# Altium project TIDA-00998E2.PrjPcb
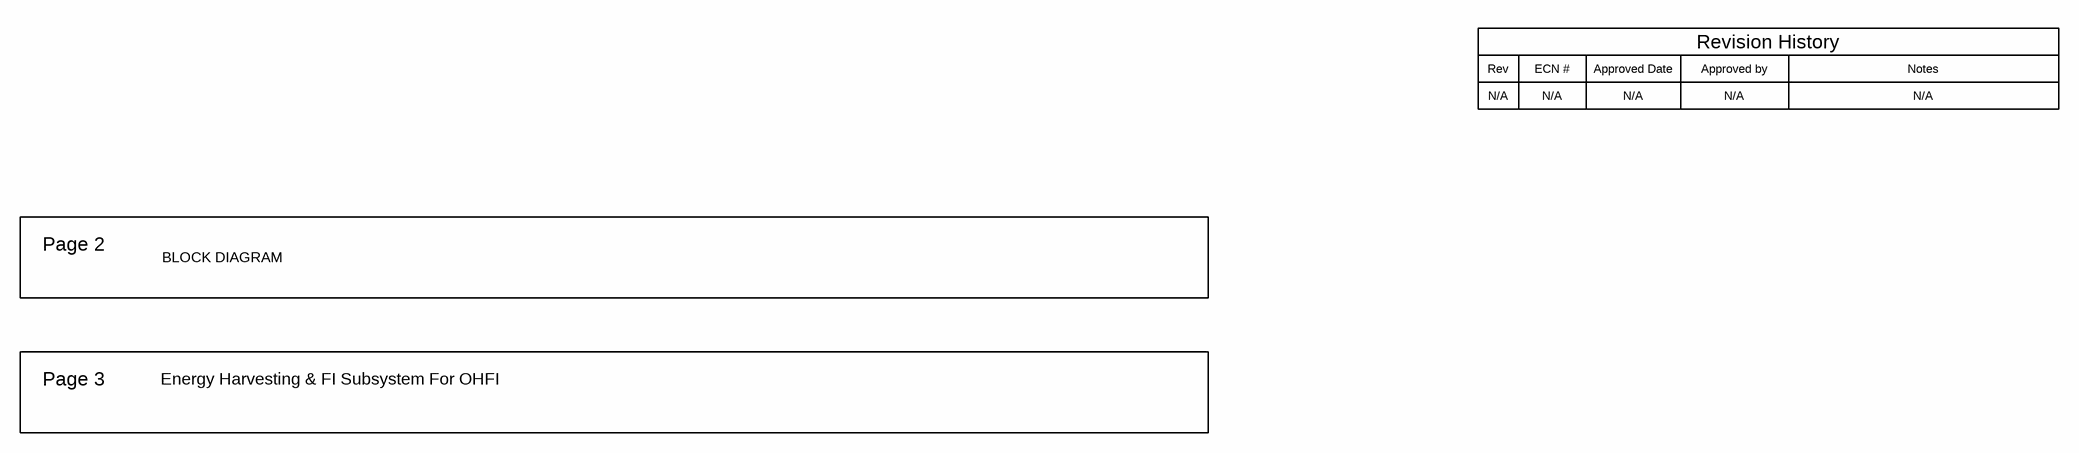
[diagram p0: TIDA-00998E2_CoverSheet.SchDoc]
CopyrightYear: 2016; EVM_Orderable: N/A; PCB_Layout: Manjunath M; PCB_Rev: E2; PRJ_Customer: Public Release; PRJ_Engineer: Murali; PRJ_Number: TIDA-00998; PRJ_Title: Energy Harvesting & FI Subsystem For OHFI; SCH_Rev: E2; TechSupport: http://www.ti.com/support; TID: TIDA-00998
4 sheets, 111 parts. Net scope: global (net labels, ports and power ports of the same name join across sheets).
Board file: TIDA-00998E2.PcbDoc
Sheets:
  TIDA-00998E2_CoverSheet.SchDoc
  TIDA-00998E2_Block Diagram.SchDoc
  TIDA-00998E2_BlankSheet.SchDoc
  TIDA-00998E2_EVM_Hardware.SchDoc

## Sheet TIDA-00998E2_CoverSheet.SchDoc
size 431 x 279 mm; Date: Not shown in title block; ApprovedBy: Not shown in title block; CheckedBy: Not shown in title block; Author: Not shown in title block; CompanyName: Not shown in title block; DrawnBy: Murali; Engineer: Not shown in title block; Organization: Not shown in title block; Address1: Not shown in title block; Address2: Not shown in title block; Address3: Not shown in title block; Address4: Not shown in title block; DocumentNumber: 1; Revision: Use project parameter SCH_Rev; SheetNumber: 1; SheetTotal: 4; PageSetup: Record=PageOptions¦CenterHorizontal=True¦CenterVertical=True¦PrintScale=1.00¦XCorrection=1.00¦YCorrection=1.00¦PrintKind=0¦BorderSize=5000000¦LeftOffset=0¦BottomOffset=0¦Orientation=2¦PaperLength=1000¦PaperWidth=1000¦Scale=100¦PaperSource=15¦PrintQuality=600¦MediaType=1¦DitherType=10¦PaperKind=Letter¦PrintScaleMode=1

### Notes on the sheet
- Rev
- N/A
- ECN #
- Approved Date
- Approved by
- Revision History
- Notes
- Page 2
- BLOCK DIAGRAM
- Page 3
- Energy Harvesting & FI Subsystem For OHFI

## Sheet TIDA-00998E2_Block Diagram.SchDoc
size 431 x 279 mm; Date: Not shown in title block; ApprovedBy: Not shown in title block; CheckedBy: Not shown in title block; Author: Not shown in title block; CompanyName: Not shown in title block; DrawnBy: Murali; Engineer: Not shown in title block; Organization: Not shown in title block; Address1: Not shown in title block; Address2: Not shown in title block; Address3: Not shown in title block; Address4: Not shown in title block; DocumentNumber: 1; Revision: Use project parameter SCH_Rev; SheetNumber: 2; SheetTotal: 4; PageSetup: Record=PageOptions¦CenterHorizontal=True¦CenterVertical=True¦PrintScale=1.00¦XCorrection=1.00¦YCorrection=1.00¦PrintKind=0¦BorderSize=5000000¦LeftOffset=0¦BottomOffset=0¦Orientation=2¦PaperLength=1000¦PaperWidth=1000¦Scale=100¦PaperSource=15¦PrintQuality=600¦MediaType=1¦DitherType=10¦PaperKind=Letter¦PrintScaleMode=1
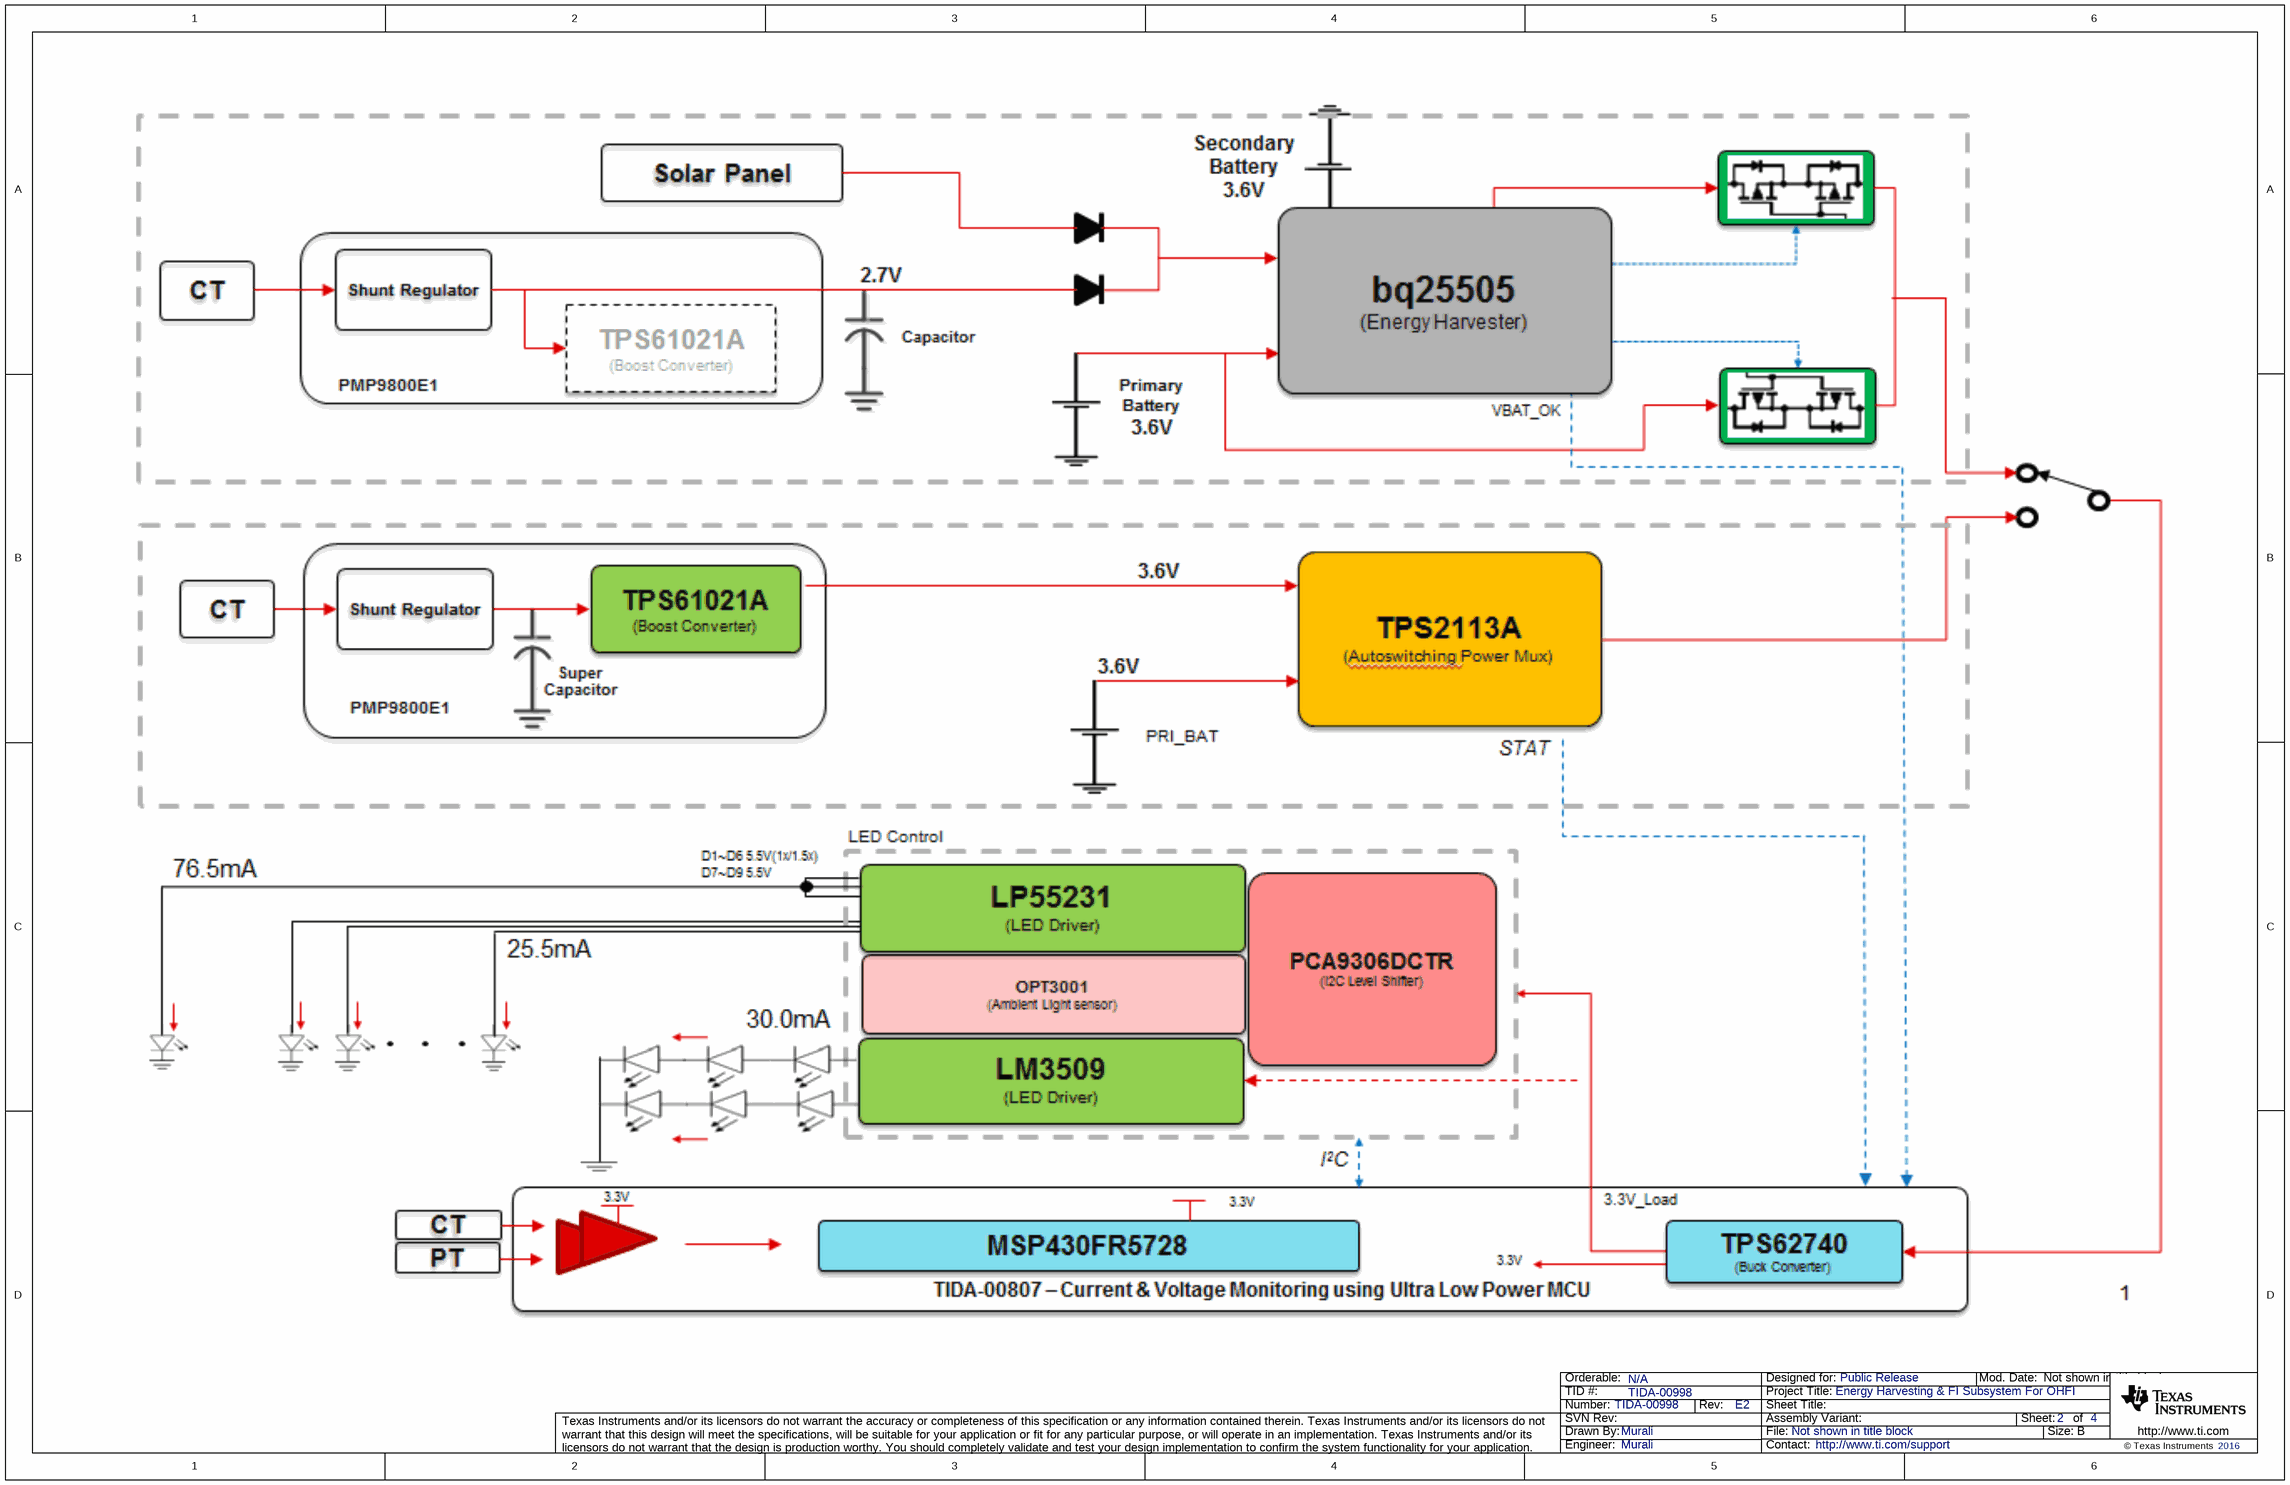
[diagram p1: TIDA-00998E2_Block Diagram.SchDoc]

## Sheet TIDA-00998E2_BlankSheet.SchDoc
size 431 x 279 mm; Date: Not shown in title block; ApprovedBy: Not shown in title block; CheckedBy: Not shown in title block; Author: Not shown in title block; CompanyName: Not shown in title block; DrawnBy: Murali; Engineer: Not shown in title block; Organization: Not shown in title block; Address1: Not shown in title block; Address2: Not shown in title block; Address3: Not shown in title block; Address4: Not shown in title block; DocumentNumber: 1; Revision: Use project parameter SCH_Rev; SheetNumber: 3; SheetTotal: 4; PageSetup: Record=PageOptions¦CenterHorizontal=True¦CenterVertical=True¦PrintScale=0.62¦XCorrection=1.00¦YCorrection=1.00¦PrintKind=0¦BorderSize=5000000¦LeftOffset=0¦BottomOffset=0¦Orientation=2¦PaperLength=1000¦PaperWidth=1000¦Scale=100¦PaperSource=15¦PrintQuality=600¦MediaType=1¦DitherType=10¦PrintScaleMode=1¦PaperKind=Letter
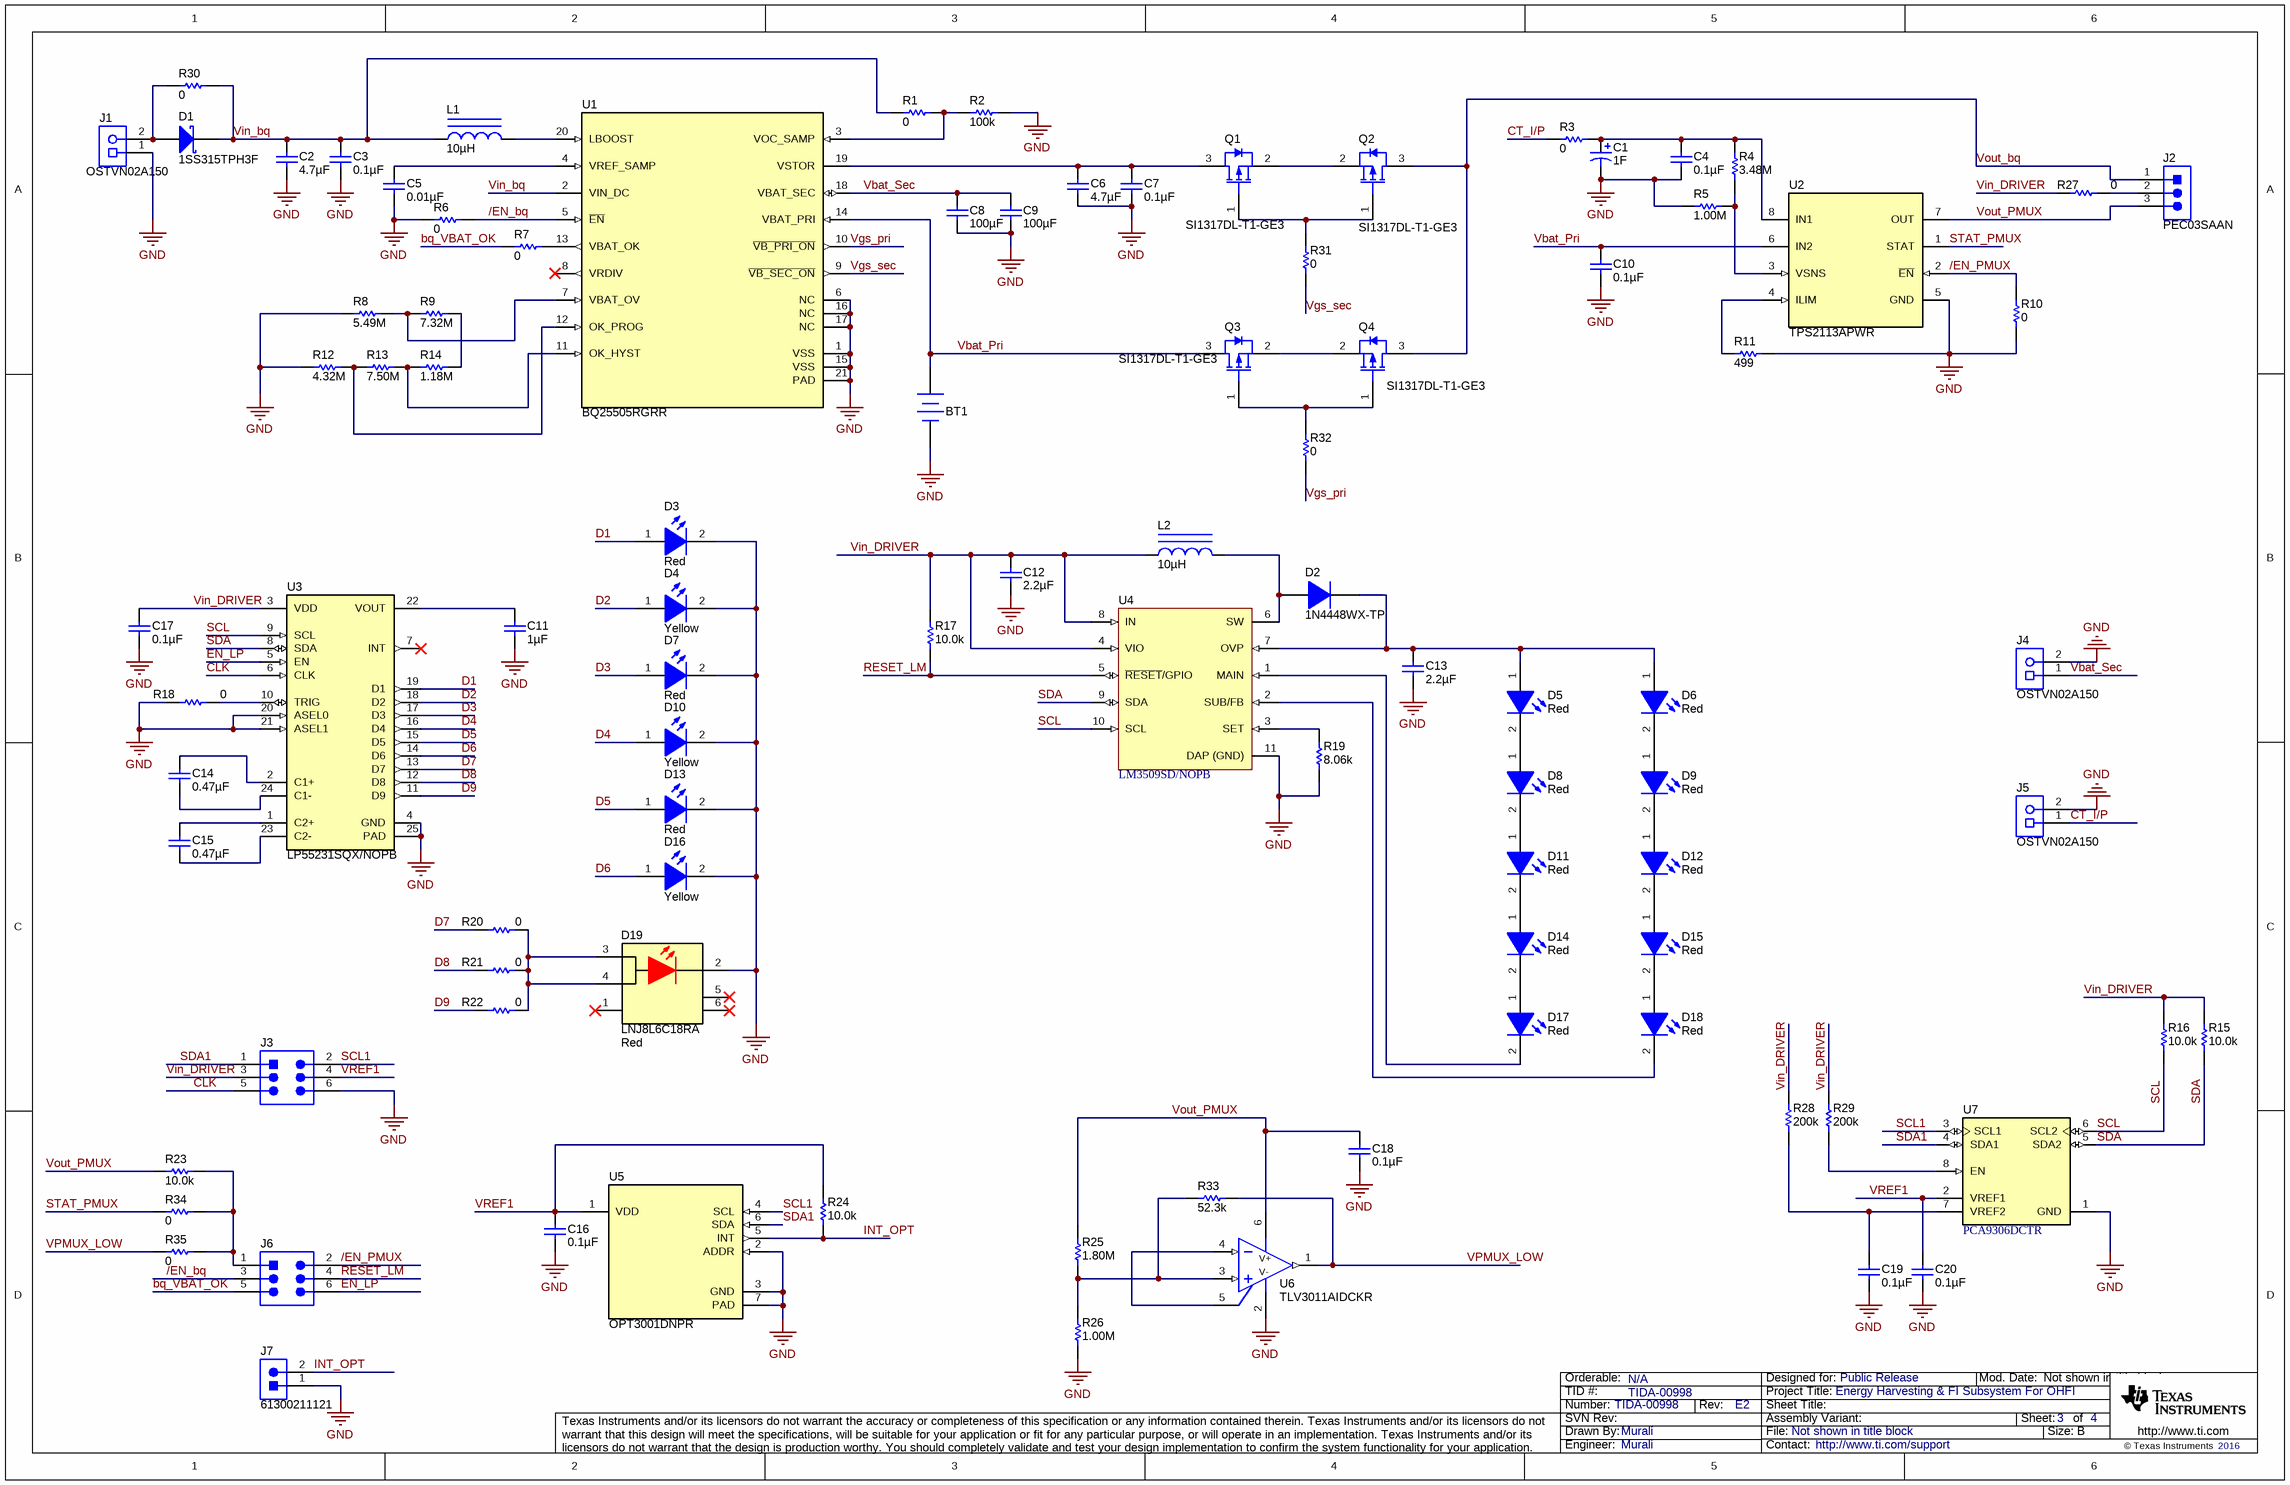
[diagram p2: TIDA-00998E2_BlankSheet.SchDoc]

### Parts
BT1  TL-4934/P  [Tadiran_TL-4934]  (value not drawn)
C1  ValueDisplayed: 1F  [DB_2150x800]  (hidden comment: DB-5R5D105T)
C2  ValueDisplayed: 4.7µF  [0603]  (hidden comment: 0603ZD475KAT2A)
C3  ValueDisplayed: 0.1µF  [0603]  (hidden comment: 06033C104JAT2A)
C4  ValueDisplayed: 0.1µF  [0603]  (hidden comment: 06033C104JAT2A)
C5  ValueDisplayed: 0.01µF  [0603]  (hidden comment: C0603C103J5RACTU)
C6  ValueDisplayed: 4.7µF  [0603]  (hidden comment: 0603ZD475KAT2A)
C7  ValueDisplayed: 0.1µF  [0603]  (hidden comment: 06033C104JAT2A)
C8  ValueDisplayed: 100µF  [1210_280]  (hidden comment: C1210C107M8PACTU)
C9  ValueDisplayed: 100µF  [1210_280]  (hidden comment: C1210C107M8PACTU)
C10  ValueDisplayed: 0.1µF  [0603]  (hidden comment: 06033C104JAT2A)
C11  ValueDisplayed: 1µF  [0603]  (hidden comment: C0603C105K8PACTU)
C12  ValueDisplayed: 2.2µF  [0805_HV]  (hidden comment: GRM219R61E225KA12D)
C13  ValueDisplayed: 2.2µF  [0805_HV]  (hidden comment: GRM219R61E225KA12D)
C14  ValueDisplayed: 0.47µF  [0603]  (hidden comment: C0603C474K8PACTU)
C15  ValueDisplayed: 0.47µF  [0603]  (hidden comment: C0603C474K8PACTU)
C16  ValueDisplayed: 0.1µF  [0603]  (hidden comment: 06033C104JAT2A)
C17  ValueDisplayed: 0.1µF  [0603]  (hidden comment: 06033C104JAT2A)
C18  ValueDisplayed: 0.1µF  [0603]  (hidden comment: 06033C104JAT2A)
C19  ValueDisplayed: 0.1µF  [0603]  (hidden comment: 06033C104JAT2A)
C20  ValueDisplayed: 0.1µF  [0603]  (hidden comment: 06033C104JAT2A)
D1  1SS315TPH3F  [SOD-323]
D2  1N4448WX-TP  [SOD-323]
D3  value Red  [HSMx-A4xx_Red]  (hidden comment: HSMZ-A400-V30M1)
D4  value Yellow  [VAOL-S2WR4_Yellow]  (hidden comment: VAOL-S2WR4)
D5  value Red  [VLMR334_Red]  (hidden comment: VLMR334BACB-GS08)
D6  value Red  [VLMR334_Red]  (hidden comment: VLMR334BACB-GS08)
D7  value Red  [HSMx-A4xx_Red]  (hidden comment: HSMZ-A400-V30M1)
D8  value Red  [VLMR334_Red]  (hidden comment: VLMR334BACB-GS08)
D9  value Red  [VLMR334_Red]  (hidden comment: VLMR334BACB-GS08)
D10  value Yellow  [VAOL-S2WR4_Yellow]  (hidden comment: VAOL-S2WR4)
D11  value Red  [VLMR334_Red]  (hidden comment: VLMR334BACB-GS08)
D12  value Red  [VLMR334_Red]  (hidden comment: VLMR334BACB-GS08)
D13  value Red  [HSMx-A4xx_Red]  (hidden comment: HSMZ-A400-V30M1)
D14  value Red  [VLMR334_Red]  (hidden comment: VLMR334BACB-GS08)
D15  value Red  [VLMR334_Red]  (hidden comment: VLMR334BACB-GS08)
D16  value Yellow  [VAOL-S2WR4_Yellow]  (hidden comment: VAOL-S2WR4)
D17  value Red  [VLMR334_Red]  (hidden comment: VLMR334BACB-GS08)
D18  value Red  [VLMR334_Red]  (hidden comment: VLMR334BACB-GS08)
D19  LNJ8L6C18RA  value Red  [LNJ8L6C18RA_Red]
J1  OSTVN02A150  [On-Shore_OSTVN02A150]
J2  PEC03SAAN  [CONN_PEC03SAAN]
J3  61300621121  [Wurth_61300621121]  (value not drawn)
J4  OSTVN02A150  [On-Shore_OSTVN02A150]
J5  OSTVN02A150  [On-Shore_OSTVN02A150]
J6  61300621121  [Wurth_61300621121]  (value not drawn)
J7  61300211121  [WURTH_61300211121]
L1  ValueDisplayed: 10µH  [VLF302515MT]  (hidden comment: VLF302515MT-100M)
L2  ValueDisplayed: 10µH  [VLF504012MT]  (hidden comment: VLF504012MT-100M)
Q1  SI1317DL-T1-GE3  [SOT-323]
Q2  SI1317DL-T1-GE3  [SOT-323]
Q3  SI1317DL-T1-GE3  [SOT-323]
Q4  SI1317DL-T1-GE3  [SOT-323]
R1  ValueDisplayed: 0  [0603]  (hidden comment: RC0603JR-070RL)
R2  ValueDisplayed: 100k  [0603]  (hidden comment: CRCW0603100KFKEA)
R3  ValueDisplayed: 0  [0603]  (hidden comment: RC0603JR-070RL)
R4  ValueDisplayed: 3.48M  [0603]  (hidden comment: CRCW06033M48FKEA)
R5  ValueDisplayed: 1.00M  [0603]  (hidden comment: CRCW06031M00FKEA)
R6  ValueDisplayed: 0  [0603]  (hidden comment: RC0603JR-070RL)
R7  ValueDisplayed: 0  [0603]  (hidden comment: RC0603JR-070RL)
R8  ValueDisplayed: 5.49M  [0603]  (hidden comment: CRCW06035M49FKEA)
R9  ValueDisplayed: 7.32M  [0603]  (hidden comment: CRCW06037M32FKEA)
R10  ValueDisplayed: 0  [0603]  (hidden comment: RC0603JR-070RL)
R11  ValueDisplayed: 499  [0603]  (hidden comment: CRCW0603499RFKEA)
R12  ValueDisplayed: 4.32M  [0603]  (hidden comment: CRCW06034M32FKEA)
R13  ValueDisplayed: 7.50M  [0603]  (hidden comment: CRCW06037M50FKEA)
R14  ValueDisplayed: 1.18M  [0603]  (hidden comment: CRCW06031M18FKEA)
R15  ValueDisplayed: 10.0k  [0603]  (hidden comment: CRCW060310K0FKEA)
R16  ValueDisplayed: 10.0k  [0603]  (hidden comment: CRCW060310K0FKEA)
R17  ValueDisplayed: 10.0k  [0603]  (hidden comment: CRCW060310K0FKEA)
R18  ValueDisplayed: 0  [0603]  (hidden comment: RC0603JR-070RL)
R19  ValueDisplayed: 8.06k  [0603]  (hidden comment: CRCW06038K06FKEA)
R20  ValueDisplayed: 0  [0603]  (hidden comment: RC0603JR-070RL)
R21  ValueDisplayed: 0  [0603]  (hidden comment: RC0603JR-070RL)
R22  ValueDisplayed: 0  [0603]  (hidden comment: RC0603JR-070RL)
R23  ValueDisplayed: 10.0k  [0603]  (hidden comment: CRCW060310K0FKEA)
R24  ValueDisplayed: 10.0k  [0603]  (hidden comment: CRCW060310K0FKEA)
R25  ValueDisplayed: 1.80M  [0603]  (hidden comment: CRCW06031M80FKEA)
R26  ValueDisplayed: 1.00M  [0603]  (hidden comment: CRCW06031M00FKEA)
R27  ValueDisplayed: 0  [0603]  (hidden comment: RC0603JR-070RL)
R28  ValueDisplayed: 200k  [0603]  (hidden comment: RC0603FR-07200KL)
R29  ValueDisplayed: 200k  [0603]  (hidden comment: RC0603FR-07200KL)
R30  ValueDisplayed: 0  [0603]  (hidden comment: RC0603JR-070RL)
R31  ValueDisplayed: 0  [0603]  (hidden comment: RC0603JR-070RL)
R32  ValueDisplayed: 0  [0603]  (hidden comment: RC0603JR-070RL)
R33  ValueDisplayed: 52.3k  [0603]  (hidden comment: CRCW060352K3FKEA)
R34  ValueDisplayed: 0  [0603]  (hidden comment: RC0603JR-070RL)
R35  ValueDisplayed: 0  [0603]  (hidden comment: RC0603JR-070RL)
U1  BQ25505RGRR  [RGR0020A]
U2  TPS2113APWR  [PW0008A_N]
U3  LP55231SQX/NOPB  [RTW0024A]
U4  LM3509SD/NOPB  [SDA10A]
U5  OPT3001DNPR  [DNP0006A]
U6  TLV3011AIDCKR  [DCK0006A_N]
U7  PCA9306DCTR  [DCT0008A_N]

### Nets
GND: BT1.2(-) C1.2(-) C2.2 C3.2 C4.2 C5.2 C6.2 C7.2 C8.2 C9.2 C10.2 C11.2 C12.1 C13.1 C16.2 C17.2 C18.2 C19.2 C20.2 D3.2(K) D4.2(K) D7.2(K) D10.2(K) D13.2(K) D16.2(K) D19.2 J1.1 J3.6 J4.2 J5.2 J7.1 R2.2 R5.1 R6.1 R8.1 R10.1 R11.1 R12.1 R18.1 R19.1 R26.1 U1.1(VSS) U1.6(NC) U1.15(VSS) U1.16(NC) U1.17(NC) U1.21(PAD) U2.5(GND) U3.4(GND) U3.20(ASEL0) U3.21(ASEL1) U3.25(PAD) U4.11(DAP_(GND)) U5.2(ADDR) U5.3(GND) U5.7(PAD) U6.2(V-) U7.1(GND)
/EN_bq: J6.3 R6.2 U1.5(~{EN})
/EN_PMUX: J6.2 R10.2 U2.2(~{EN})
bq_VBAT_OK: J6.5 R7.1
CLK: J3.5 U3.6(CLK)
CT_I/P: J5.1 R3.1
D1: D3.1(A) U3.19(D1)
D2: D4.1(A) U3.18(D2)
D3: D7.1(A) U3.17(D3)
D4: D10.1(A) U3.16(D4)
D5: D13.1(A) U3.15(D5)
D6: D16.1(A) U3.14(D6)
D7: R20.1 U3.13(D7)
D8: R21.1 U3.12(D8)
D9: R22.1 U3.11(D9)
EN_LP: J6.6 U3.5(EN)
INT_OPT: J7.2 R24.1 U5.5(INT)
RESET_LM: J6.4 R17.1 U4.5(~{RESET}/GPIO)
SCL: R16.1 U3.9(SCL) U4.10(SCL) U7.6(SCL2)
SCL1: J3.2 U5.4(SCL) U7.3(SCL1)
SDA: R15.1 U3.8(SDA) U4.9(SDA) U7.5(SDA2)
SDA1: J3.1 U5.6(SDA) U7.4(SDA1)
STAT_PMUX: R34.1 U2.1(STAT)
Vbat_Pri: BT1.1(+) C10.1 Q3.3(D) U1.14(VBAT_PRI) U2.6(IN2)
Vbat_Sec: C8.1 C9.1 J4.1 U1.18(VBAT_SEC)
Vgs_pri: R32.1 U1.10(~{VB_PRI_ON})
Vgs_sec: R31.1 U1.9(~{VB_SEC_ON})
Vin_bq: C2.1 C3.1 D1.1(K) L1.1 R1.1 R30.2 U1.2(VIN_DC)
Vin_DRIVER: C12.2 C17.1 J3.3 L2.1 R15.2 R16.2 R17.2 R27.1 R28.2 R29.2 U3.3(VDD) U4.4(VIO) U4.8(IN)
Vout_bq: J2.1 Q2.3(D) Q4.3(D)
Vout_PMUX: C18.1 J2.3 R23.2 R25.2 U2.7(OUT) U6.6(V+)
VPMUX_LOW: R33.2 R35.1 U6.1(OUT)
VREF1: C16.1 C20.1 J3.4 R24.2 U5.1(VDD) U7.2(VREF1)
NetC1_1: C1.1(+) C4.1 R3.2 R4.2 U2.8(IN1)
NetC5_1: C5.1 U1.4(VREF_SAMP)
NetC6_1: C6.1 C7.1 Q1.3(D) U1.19(VSTOR)
NetC11_1: C11.1 U3.22(VOUT)
NetC13_2: C13.2 D2.1(K) D5.1(A) D6.1(A) U4.7(OVP)
NetC14_1: C14.1 U3.2(C1+)
NetC14_2: C14.2 U3.24(C1-)
NetC15_1: C15.1 U3.1(C2+)
NetC15_2: C15.2 U3.23(C2-)
NetC19_1: C19.1 R28.1 U7.7(VREF2)
NetD1_2: D1.2(A) J1.2 R30.1
NetD2_2: D2.2(A) L2.2 U4.6(SW)
NetD5_2: D5.2(K) D8.1(A)
NetD6_2: D6.2(K) D9.1(A)
NetD8_2: D8.2(K) D11.1(A)
NetD9_2: D9.2(K) D12.1(A)
NetD11_2: D11.2(K) D14.1(A)
NetD12_2: D12.2(K) D15.1(A)
NetD14_2: D14.2(K) D17.1(A)
NetD15_2: D15.2(K) D18.1(A)
NetD17_2: D17.2(K) U4.1(MAIN)
NetD18_2: D18.2(K) U4.2(SUB/FB)
NetD19_3: D19.3 D19.4 R20.2 R21.2 R22.2
NetJ2_2: J2.2 R27.2
NetJ6_1: J6.1 R23.1 R34.2 R35.2
NetL1_2: L1.2 U1.20(LBOOST)
NetQ1_1: Q1.1(G) Q2.1(G) R31.2
NetQ1_2: Q1.2(S) Q2.2(S)
NetQ3_1: Q3.1(G) Q4.1(G) R32.2
NetQ3_2: Q3.2(S) Q4.2(S)
NetR1_2: R1.2 R2.1 U1.3(VOC_SAMP)
NetR4_1: R4.1 R5.2 U2.3(VSNS)
NetR7_2: R7.2 U1.13(VBAT_OK)
NetR8_2: R8.2 R9.1 U1.7(VBAT_OV)
NetR9_2: R9.2 R14.2
NetR11_2: R11.2 U2.4(ILIM)
NetR12_2: R12.2 R13.1 U1.12(OK_PROG)
NetR13_2: R13.2 R14.1 U1.11(OK_HYST)
NetR18_2: R18.2 U3.10(TRIG)
NetR19_2: R19.2 U4.3(SET)
NetR25_1: R25.1 R26.2 R33.1 U6.3(IN+)
NetR29_1: R29.1 U7.8(EN)
NetU6_4: U6.4(IN-) U6.5(REF)

Not connected (* = marked no-connect by the designer): D19 1* 5* 6*; U1 8(VRDIV)*; U3 7(INT)*

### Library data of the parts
BT1 = TL-4934/P: Battery 3.6V, TH; Manufacturer: Tadiran Batteries
C1 = DB-5R5D105T: CAP, Electric Double Layer, 1F, 5.5 V, +80/-20%, 30 ohm, TH; Manufacturer: Elna; Polarized: Y; CompType: Capacitor; Value: 1000000uF; U/M: EA; Cap_F: 1; Tolerance_%: 80; Value1: 30 ohm; VDC_V: 5.5; Value2: 5.5V; ESR_ohm: 30; TaMin_C: -25; TaMax_C: 70; Cap_Case: 21.5x8; SizeAreaWB_mm2: 552.25; SizeArea_mm2: 462.25; SizeX_mm: 21.5; SizeZ_mm: 12.5; AEC Category: Q200; AEC Qualified: N
C2 C6 = 0603ZD475KAT2A: CAP, CERM, 4.7 µF, 10 V, +/- 10%, X5R, 0603; Manufacturer: AVX; Polarized: N; CompType: Capacitor; Value: 4.7uF; U/M: EA; Cap_F: 0.0000047; Tolerance_%: 10; Value1: Unknown; Value2: 10V; TaMin_C: -55; TaMax_C: 85; SizeArea_mm2: 1.28; SizeAreaWB_mm2: 4.68; SizeX_mm: 1.6; SizeY_mm: 0.8; SizeZ_mm: 1; AEC Category: Q200
C3 C4 C7 C10 C16-C20 = 06033C104JAT2A: CAP, CERM, 0.1 µF, 25 V, +/- 5%, X7R, 0603; Manufacturer: AVX; Polarized: N; CompType: Capacitor; Value: 0.1uF; U/M: EA; Cap_F: 0.0000001; Tolerance_%: 5; ESR_ohm: 0.05; Value1: 0.05 ohm; VDC_V: 25; Value2: 25V; TaMin_C: -55; TaMax_C: 125; AEC Category: Q200
C5 = C0603C103J5RACTU: CAP, CERM, 0.01 µF, 50 V, +/- 5%, X7R, 0603; Manufacturer: Kemet; Polarized: N; CompType: Capacitor; Value: 0.01uF; U/M: EA; Cap_F: 0.00000001; Tolerance_%: 5; Value1: Unknown; VDC_V: 50; Value2: 50V; TaMin_C: -55; TaMax_C: 125; SizeArea_mm2: 1.28; SizeAreaWB_mm2: 4.68; SizeX_mm: 1.6; SizeY_mm: 0.8; SizeZ_mm: 1; AEC Category: Q200
C8 C9 = C1210C107M8PACTU: CAP, CERM, 100 µF, 10 V, +/- 20%, X5R, 1210; Manufacturer: Wurth Elektronik; Polarized: N; CompType: Capacitor; Value: 100uF; U/M: EA; Cap_F: 0.0001; Tolerance_%: 20; Value1: Unknown; VDC_V: 10; Value2: 10V; TaMin_C: -55; TaMax_C: 85; Cap_Case: 1210; SizeArea_mm2: 8; SizeAreaWB_mm2: 14.7; SizeX_mm: 3.2; SizeY_mm: 2.5; SizeZ_mm: 2.8; AEC Category: Q200
C11 = C0603C105K8PACTU: CAP, CERM, 1 µF, 10 V, +/- 10%, X5R, 0603; Manufacturer: Kemet; Polarized: N; CompType: Capacitor; Value: 1uF; U/M: EA; Cap_F: 0.000001; Tolerance_%: 10; Value1: Unknown; Value2: 10V; TaMin_C: -55; TaMax_C: 85; SizeArea_mm2: 1.28; SizeAreaWB_mm2: 4.68; SizeX_mm: 1.6; SizeY_mm: 0.8; SizeZ_mm: 1; AEC Category: Q200
C12 C13 = GRM219R61E225KA12D: CAP, CERM, 2.2 µF, 25 V, +/- 10%, X5R, 0805; Manufacturer: MuRata; Polarized: N; CompType: Capacitor; Value: 2.2uF; U/M: EA; Cap_F: 0.0000022; Tolerance_%: 10; ESR_ohm: 0.006; Value1: 0.006 ohm; VDC_V: 25; Value2: 25V; TaMin_C: -55; TaMax_C: 85; Cap_Case: 0805; SizeArea_mm2: 2.5; SizeAreaWB_mm2: 6.75; SizeX_mm: 2; SizeY_mm: 1.25; SizeZ_mm: 1.45; AEC Category: Q200
C14 C15 = C0603C474K8PACTU: CAP, CERM, 0.47 µF, 10 V, +/- 10%, X5R, 0603; Manufacturer: Kemet; Polarized: N; CompType: Capacitor; Value: 0.47uF; U/M: EA; Cap_F: 0.00000047; Tolerance_%: 10; Value1: Unknown; Value2: 10V; TaMin_C: -55; TaMax_C: 85; SizeArea_mm2: 1.28; SizeAreaWB_mm2: 4.68; SizeX_mm: 1.6; SizeY_mm: 0.8; SizeZ_mm: 1; AEC Category: Q200
D1 = 1SS315TPH3F: Diode, Schottky, 5 V, 0.03 A, SOD-323; Manufacturer: Toshiba; U/M: EA; Vf_V: 0.38; Value: 5V; Value1: 0.03A; Value2: 0.38V; Io_A: 0.03; Vr_V: 5; TJmax_C: 125; SizeAreaWB_mm2: 8.695; SizeArea_mm2: 3.645; SizeX_mm: 2.7; SizeY_mm: 1.35; SizeZ_mm: 1; AEC Category: Q101
D2 = 1N4448WX-TP: Diode, Switching, 75 V, 0.25 A, SOD-323; Manufacturer: Micro Commercial Components; U/M: EA; Value: 75V; Value1: 0.25A; Io_A: 0.25; Vr_V: 75; TJmax_C: 150; SizeAreaWB_mm2: 8.695; SizeArea_mm2: 3.645; SizeX_mm: 2.7; SizeY_mm: 1.35; SizeZ_mm: 1; AEC Category: Q101
D3 D7 D13 = HSMZ-A400-V30M1: LED, Red, SMD; Manufacturer: Avago; Type: AlInGaP; Vf_V: 2.8; Value2: 2.8V; Io_A: 0.05; Vr_V: 5; Tjmax_C: 110; Power_TotalModule: 0.24; Value1: 0.24W; Angle: 120; SizeAreaWB_mm2: 17.1; SizeArea_mm2: 9.8; SizeY_mm: 3.5; SizeZ_mm: 2.1; U/M: EA
D4 D10 D16 = VAOL-S2WR4: LED, Yellow, SMD; Manufacturer: Visual Communications Company, LLC; Type: InGaN; Vf_V: 3.1; Value2: 3.1V; Io_A: 0.02; Vr_V: 5; Tjmax_C: 85; Power_TotalModule: 0.11; Value1: 0.11W; Angle: 120; SizeAreaWB_mm2: 16.65; SizeArea_mm2: 9.45; SizeX_mm: 3.5; SizeY_mm: 2.7; SizeZ_mm: 2.1; U/M: EA
D5 D6 D8 D9 D11 D12 D14 D15 D17 D18 = VLMR334BACB-GS08: LED, Red, SMD; Manufacturer: Vishay-Semiconductor; Type: AlInGaP; Vf_V: 2.2; Value2: 2.2V; Io_A: 0.05; Vr_V: 5; Ir_A: 1e-005; Tjmax_C: 125; Power_TotalModule: 0.2; Value1: 0.2W; Angle: 120; SizeAreaWB_mm2: 17.1; SizeArea_mm2: 9.8; SizeX_mm: 3.5; SizeY_mm: 2.8; SizeZ_mm: 1.85; U/M: EA
D19 = LNJ8L6C18RA: LED, Red, SMD; Manufacturer: Panasonic; SymbolCreator: Altium; Vf_V: 2.45; Value2: 2.45V; Io_A: 0.14; Vr_V: 5; Ir_A: 1e-005; Tjmax_C: 125; Value1: W; U/M: EA
J1 J4 J5 = OSTVN02A150: Terminal Block, 2.54mm, 2x1, Brass, TH; Manufacturer: On-Shore Technology; SymbolCreator: a0412235
J2 = PEC03SAAN: Header, 100mil, 3x1, Tin, TH; Manufacturer: Sullins Connector Solutions; SymbolCreator: a0799628; Pitch_mm: 2.54; Gender: Male; Shrouded: N; Row_Count: 1; Current_A: 3; Voltage_V: 1800; Cert_UL: Y
J3 J6 = 61300621121: Header, 2.54mm, 3x2, Gold, TH; Manufacturer: Wurth Elektronik; SymbolCreator: a0412235; Pitch_mm: 2.54; Gender: Male; Shrouded: N; Row_Count: 2
J7 = 61300211121: Header, 2.54 mm, 2x1, Gold, TH; Manufacturer: Wurth Elektronik; SymbolCreator: a0412235
L1 = VLF302515MT-100M: Inductor, Shielded, Ferrite, 10 µH, 0.71 A, 0.152 ohm, SMD; Manufacturer: TDK; Value: 10uH; Ind_H: 10.0E-6; Imax_A: 0.71; Irms: 1.37A @ 40C rise; Isat: 0.71A @ 30% inductance drop; DCR_ohm: 0.152; Value2: 0.71A; AEC Category: Q200
L2 = VLF504012MT-100M: Inductor, Shielded, Ferrite, 10 µH, 1.3 A, 0.19 ohm, SMD; Manufacturer: TDK; Value: 10uH; Ind_H: 10.0E-6; Imax_A: 1.3; Irms: 1.3A @ 40C rise; Isat: 1.32A @ 30% inductance drop; DCR_ohm: 0.19; Value2: 1.3A; AEC Category: Q200
Q1-Q4 = SI1317DL-T1-GE3: MOSFET, P-CH, -20 V, -1.4 A, SOT-323; Manufacturer: Vishay-Siliconix; Alternate Manufacturer: None; U/M: EA; ChType: P; Value: -20V; Value1: 0.15 ohm; Rdson45_ohm: 0.15; Value2: 4.3 nC; QgTyp_nC: 4.3; Vgs_V: -8; SizeAreaWB_mm2: 10.24; SizeArea_mm2: 4.84; SizeX_mm: 2.2; SizeZ_mm: 1.1; AEC Category: Q101
R1 R3 R6 R7 R10 R18 R20-R22 R27 R30-R32 R34 R35 = RC0603JR-070RL: RES, 0, 5%, 0.1 W, 0603; Manufacturer: Yageo America; CompType: Resistor; Value: 0; Value_Code: 0000; Tolerance_%: 5; Power_W: 0.1; Value2: 0.1W; VDC_V: 50; TempCo: 200 ppm/C; EIA_Code: E24; U/M: EA; AEC Category: Q200
R2 = CRCW0603100KFKEA: RES, 100 k, 1%, 0.1 W, 0603; Manufacturer: Vishay-Dale; CompType: Resistor; Value: 100k; Res_ohm: 100000; Tolerance_%: 1; Power_W: 0.1; Value2: 0.1W; VDC_V: 75; TempCo: 100 ppm/C; SizeArea_mm2: 1.28; SizeX_mm: 1.6; SizeY_mm: 0.8; EIA_Code: E96; U/M: EA; AEC Category: Q200
R4 = CRCW06033M48FKEA: RES, 3.48 M, 1%, 0.1 W, 0603; Manufacturer: Vishay-Dale; CompType: Resistor; Value: 3.48Meg; Res_ohm: 3480000; Value_Code: 3M48; Tolerance_%: 1; Power_W: 0.1; Value2: 0.1W; VDC_V: 75; TempCo: 100 ppm/C; SizeArea_mm2: 1.28; SizeX_mm: 1.6; SizeY_mm: 0.8; EIA_Code: E96; U/M: EA; AEC Category: Q200
R5 R26 = CRCW06031M00FKEA: RES, 1.00 M, 1%, 0.1 W, 0603; Manufacturer: Vishay-Dale; CompType: Resistor; Value: 1.00Meg; Res_ohm: 1000000; Value_Code: 1M00; Tolerance_%: 1; Power_W: 0.1; Value2: 0.1W; VDC_V: 75; TempCo: 100 ppm/C; SizeArea_mm2: 1.28; SizeX_mm: 1.6; SizeY_mm: 0.8; EIA_Code: E96; U/M: EA; AEC Category: Q200
R8 = CRCW06035M49FKEA: RES, 5.49 M, 1%, 0.1 W, 0603; Manufacturer: Vishay-Dale; CompType: Resistor; Value: 5.49Meg; Res_ohm: 5490000; Value_Code: 5M49; Tolerance_%: 1; Power_W: 0.1; Value2: 0.1W; VDC_V: 75; TempCo: 100 ppm/C; SizeArea_mm2: 1.28; SizeX_mm: 1.6; SizeY_mm: 0.8; EIA_Code: E96; U/M: EA; AEC Category: Q200
R9 = CRCW06037M32FKEA: RES, 7.32 M, 1%, 0.1 W, 0603; Manufacturer: Vishay-Dale; CompType: Resistor; Value: 7.32Meg; Res_ohm: 7320000; Value_Code: 7M32; Tolerance_%: 1; Power_W: 0.1; Value2: 0.1W; VDC_V: 75; TempCo: 100 ppm/C; SizeArea_mm2: 1.28; SizeX_mm: 1.6; SizeY_mm: 0.8; EIA_Code: E96; U/M: EA; AEC Category: Q200
R11 = CRCW0603499RFKEA: RES, 499, 1%, 0.1 W, 0603; Manufacturer: Vishay-Dale; CompType: Resistor; Value: 499; Value_Code: 499R; Tolerance_%: 1; Power_W: 0.1; Value2: 0.1W; VDC_V: 75; TempCo: 100 ppm/C; SizeArea_mm2: 1.28; SizeX_mm: 1.6; SizeY_mm: 0.8; EIA_Code: E96; U/M: EA; AEC Category: Q200
R12 = CRCW06034M32FKEA: RES, 4.32 M, 1%, 0.1 W, 0603; Manufacturer: Vishay-Dale; CompType: Resistor; Value: 4.32Meg; Res_ohm: 4320000; Value_Code: 4M32; Tolerance_%: 1; Power_W: 0.1; Value2: 0.1W; VDC_V: 75; TempCo: 100 ppm/C; SizeArea_mm2: 1.28; SizeX_mm: 1.6; SizeY_mm: 0.8; EIA_Code: E96; U/M: EA; AEC Category: Q200
R13 = CRCW06037M50FKEA: RES, 7.50 M, 1%, 0.1 W, 0603; Manufacturer: Vishay-Dale; CompType: Resistor; Value: 7.50Meg; Res_ohm: 7500000; Value_Code: 7M50; Tolerance_%: 1; Power_W: 0.1; Value2: 0.1W; VDC_V: 75; TempCo: 100 ppm/C; SizeArea_mm2: 1.28; SizeX_mm: 1.6; SizeY_mm: 0.8; EIA_Code: E96; U/M: EA; AEC Category: Q200
R14 = CRCW06031M18FKEA: RES, 1.18 M, 1%, 0.1 W, 0603; Manufacturer: Vishay-Dale; CompType: Resistor; Value: 1.18Meg; Res_ohm: 1180000; Value_Code: 1M18; Tolerance_%: 1; Power_W: 0.1; Value2: 0.1W; VDC_V: 75; TempCo: 100 ppm/C; SizeArea_mm2: 1.28; SizeX_mm: 1.6; SizeY_mm: 0.8; EIA_Code: E96; U/M: EA; AEC Category: Q200
R15-R17 R23 R24 = CRCW060310K0FKEA: RES, 10.0 k, 1%, 0.1 W, 0603; Manufacturer: Vishay-Dale; CompType: Resistor; Value: 10.0k; Res_ohm: 10000; Value_Code: 10k0; Tolerance_%: 1; Power_W: 0.1; Value2: 0.1W; VDC_V: 75; TempCo: 100 ppm/C; SizeArea_mm2: 1.28; SizeX_mm: 1.6; SizeY_mm: 0.8; EIA_Code: E96; U/M: EA; AEC Category: Q200
R19 = CRCW06038K06FKEA: RES, 8.06 k, 1%, 0.1 W, 0603; Manufacturer: Vishay-Dale; CompType: Resistor; Value: 8.06k; Res_ohm: 8060; Value_Code: 8k06; Tolerance_%: 1; Power_W: 0.1; Value2: 0.1W; VDC_V: 75; TempCo: 100 ppm/C; SizeArea_mm2: 1.28; SizeX_mm: 1.6; SizeY_mm: 0.8; EIA_Code: E96; U/M: EA; AEC Category: Q200
R25 = CRCW06031M80FKEA: RES, 1.80 M, 1%, 0.1 W, AEC-Q200 Grade 0, 0603; Manufacturer: Vishay-Dale; CompType: Resistor; Value: 1.80Meg; Res_ohm: 1800000; Value_Code: 1M80; Tolerance_%: 1; Power_W: 0.1; Value2: 0.1W; VDC_V: 75; TempCo: 100 ppm/C; SizeArea_mm2: 1.28; SizeX_mm: 1.6; SizeY_mm: 0.8; U/M: EA; AEC Category: Q200; AEC Qualified: Y; AEC Grade: 0
R28 R29 = RC0603FR-07200KL: RES, 200 k, 1%, 0.1 W, 0603; Manufacturer: Yageo America; CompType: Resistor; Value: 200k; Res_ohm: 200000; Tolerance_%: 1; Power_W: 0.1; Value2: 0.1W; VDC_V: 150; TempCo: 200 ppm/C; SizeArea_mm2: 1.28; SizeX_mm: 1.6; SizeY_mm: 0.8; EIA_Code: E96; U/M: EA; AEC Category: Q200
R33 = CRCW060352K3FKEA: RES, 52.3 k, 1%, 0.1 W, 0603; Manufacturer: Vishay-Dale; CompType: Resistor; Value: 52.3k; Res_ohm: 52300; Value_Code: 52k3; Tolerance_%: 1; Power_W: 0.1; Value2: 0.1W; VDC_V: 75; TempCo: 100 ppm/C; SizeArea_mm2: 1.28; SizeX_mm: 1.6; SizeY_mm: 0.8; EIA_Code: E96; U/M: EA; AEC Category: Q200
U1 = BQ25505RGRR: Ultra Low Power Boost Converter with Battery Management for Energy Harvester Applications, RGR0020A (VQFN-20); Alternate PartNumber: BQ25505RGRT; Manufacturer: Texas Instruments; SymbolCreator: a0412235; SizeArea_mm2: 12.25; SizeAreaWB_mm2: 20.25; SizeX_mm: 3.5; SizeZ_mm: 1; CompType: IC; U/M: EA
U2 = TPS2113APWR: AUTOSWITCHING POWER MUX, PW0008A (TSSOP-8); Manufacturer: Texas Instruments; SymbolCreator: Altium; SizeArea_mm2: 19.2; SizeAreaWB_mm2: 42; SizeX_mm: 6.4; SizeY_mm: 3; SizeZ_mm: 1.2; CompType: IC; U/M: EA
U3 = LP55231SQX/NOPB: LP55231 Programmable 9-Output LED Driver, RTW0024A (WQFN-24); Manufacturer: Texas Instruments; SymbolCreator: x0208325; SizeArea_mm2: 16; SizeAreaWB_mm2: 25; SizeX_mm: 4; SizeZ_mm: 0.8; CompType: IC; U/M: EA
U4 = LM3509SD/NOPB: High Efficiency Boost for White LED's and/or OLED Displays with Dual Current Sinks and IC Compatible Brightness Control, 10-pin LLP, Pb-Free; Manufacturer: Texas Instruments; PackageTopMarking: ZXYTT*L3509; PowerWise: Y; CompType: MiscPower
U5 = OPT3001DNPR: Ambient Light Sensor, DNP0006A (USON-6); Alternate PartNumber: OPT3001DNPT; Manufacturer: Texas Instruments; SymbolCreator: a0411947; SizeArea_mm2: 4; SizeAreaWB_mm2: 9; SizeX_mm: 2; SizeZ_mm: 0.65; CompType: IC; U/M: EA
U6 = TLV3011AIDCKR: Nanopower, 1.8V, Comparator with Voltage Reference, DCK0006A (SOT-6); Alternate PartNumber: TLV3011AIDCKT; Manufacturer: Texas Instruments; SymbolCreator: a0411595/a0412235; SizeArea_mm2: 4.2; SizeAreaWB_mm2: 9.3; SizeX_mm: 2.1; SizeY_mm: 2; SizeZ_mm: 1.1; CompType: IC; U/M: EA
U7 = PCA9306DCTR: Dual Bi-Directional I2C-Bus and SMBus Voltage Level-Translator, 0 to 5.5 V, -40 to 85 degC, 8-pin SM8 (DCT), Green (RoHS & no Sb/Br); Manufacturer: Texas Instruments; Alternate PartNumber: Equivalent; SubFamily: I2C Special Function; No. of Outputs: 2; tpd max(ns): 1.5; fSCLK(Max)(MHz): 400; Function: Voltage Translator; Vcc range(V): 0 to 5.5; Enable Pin: Yes; Rating: Catalog

## Sheet TIDA-00998E2_EVM_Hardware.SchDoc
size 431 x 279 mm; Date: Not shown in title block; ApprovedBy: Not shown in title block; CheckedBy: Not shown in title block; Author: Not shown in title block; CompanyName: Not shown in title block; DrawnBy: Murali; Engineer: Not shown in title block; Organization: Not shown in title block; Address1: Not shown in title block; Address2: Not shown in title block; Address3: Not shown in title block; Address4: Not shown in title block; DocumentNumber: 1; Revision: Use project parameter SCH_Rev; SheetNumber: 4; SheetTotal: 4; PageSetup: Record=PageOptions¦CenterHorizontal=True¦CenterVertical=True¦PrintScale=1.00¦XCorrection=1.00¦YCorrection=1.00¦PrintKind=0¦BorderSize=5000000¦LeftOffset=0¦BottomOffset=0¦Orientation=2¦PaperLength=1000¦PaperWidth=1000¦Scale=100¦PaperSource=15¦PrintQuality=600¦MediaType=1¦DitherType=10¦PaperKind=Letter¦PrintScaleMode=1
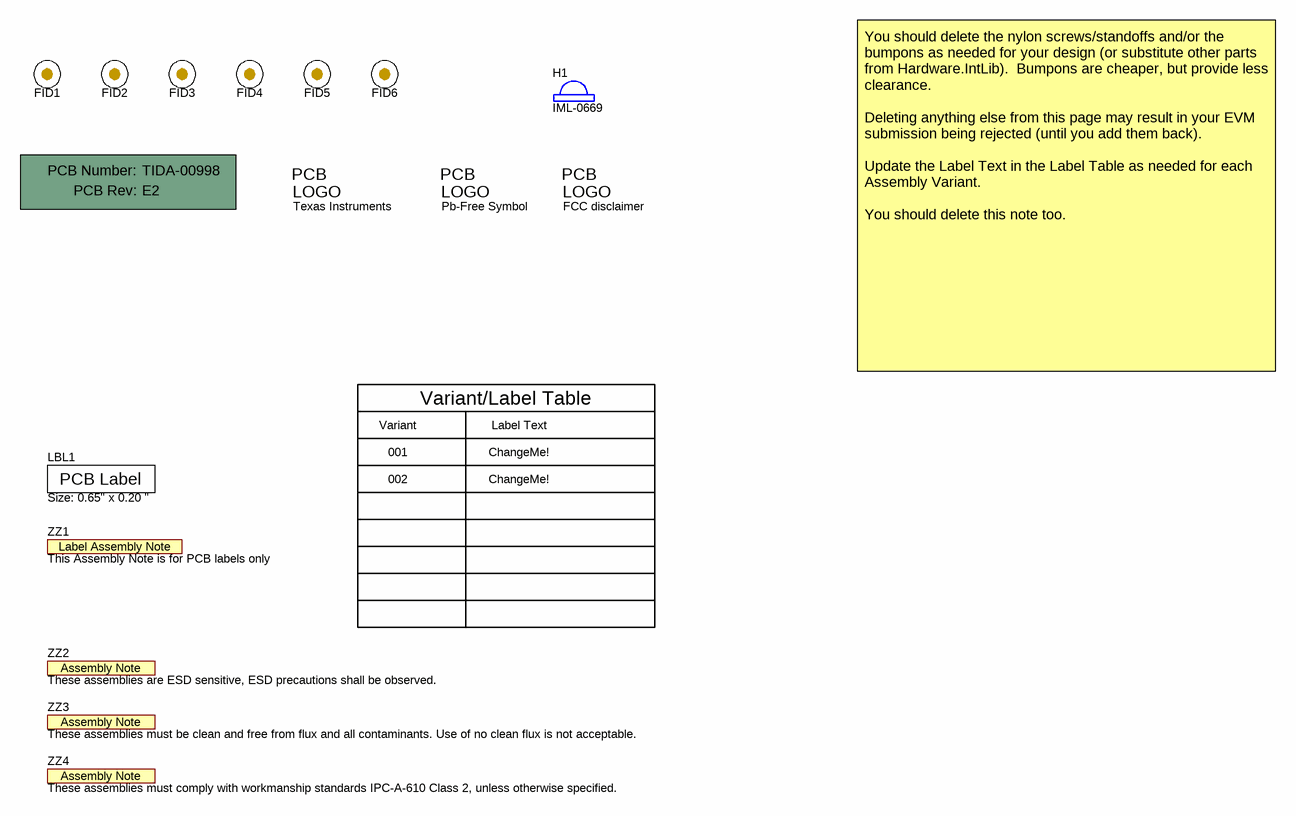
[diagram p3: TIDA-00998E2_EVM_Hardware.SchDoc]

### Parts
!PCB  Printed Circuit Board  (value not drawn)  (mechanical)
FID1  Fiducial  [Fiducial10-20]  (value not drawn)
FID2  Fiducial  [Fiducial10-20]  (value not drawn)
FID3  Fiducial  [Fiducial10-20]  (value not drawn)
FID4  Fiducial  [Fiducial10-20]  (value not drawn)
FID5  Fiducial  [Fiducial10-20]  (value not drawn)
FID6  Fiducial  [Fiducial10-20]  (value not drawn)
H1  IML-0669  [Murata_IML-0669]
LBL1  Size: 0.65" x 0.20 "  [Label_650x200]
Logo1  Texas Instruments  [TI_Stacked_Overlay_Small]  (no BOM)
Logo2  Pb-Free Symbol  [Pb-Free_Overlay_Small]  (no BOM)
Logo3  FCC disclaimer  [FCC_disclaimer]  (no BOM)
ZZ1  This Assembly Note is for PCB labels only  [AssemblyNoteLabel]  (no BOM)
ZZ2  These assemblies are ESD sensitive, ESD precautions shall be observed.  [AssemblyNote]  (no BOM)
ZZ3  These assemblies must be clean and free from flux and all contaminants. Use of no clean flux is not acceptable.  [AssemblyNote]  (no BOM)
ZZ4  These assemblies must comply with workmanship standards IPC-A-610 Class 2, unless otherwise specified.  [AssemblyNote]  (no BOM)

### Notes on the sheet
- Variant
- Variant/Label Table
- Label Text
- You should delete the nylon screws/standoffs and/or the bumpons as needed for your design (or substitute other parts from Hardware.IntLib).  Bumpons are cheaper, but provide less clearance.
  Deleting anything else from this page may result in your EVM submission being rejected (until you add them back).
  Update the Label Text in the Label Table as needed for each Assembly Variant.
  You should delete this note too.
- 001
- 002
- ChangeMe!

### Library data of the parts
!PCB = PCB: Manufacturer: Any; PartNumber: TIDA-00998; SymbolCreator: a0412235
FID1-FID6 = Fiducial: Fiducial mark.  There is nothing to buy or mount.; SymbolCreator: codlsc
H1 = IML-0669: Lens, Ceiling Mount, TH; Manufacturer: MuRata; SymbolCreator: Altium
LBL1 = THT-14-423-10: Thermal Transfer Printable Labels, 0.650" W x 0.200" H - 10,000 per roll; Manufacturer: Brady; SymbolCreator: a0412235; CompType: Label
Logo1 = TI_Logo: Texas Instrument Corporate Signature; SymbolCreator: codlsc
Logo2 = Pb-Free: SymbolCreator: a0412235
Logo3 = FCC_disclaimer: SymbolCreator: codlsc
ZZ1 = AssemblyNoteLabel: SymbolCreator: a0412235
ZZ2-ZZ4 = AssemblyNote: SymbolCreator: codlsc

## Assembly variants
001: not fitted BT1 C1 C18 D1 FID1 FID2 FID3 R2 R25 R26 R33 R35 U6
